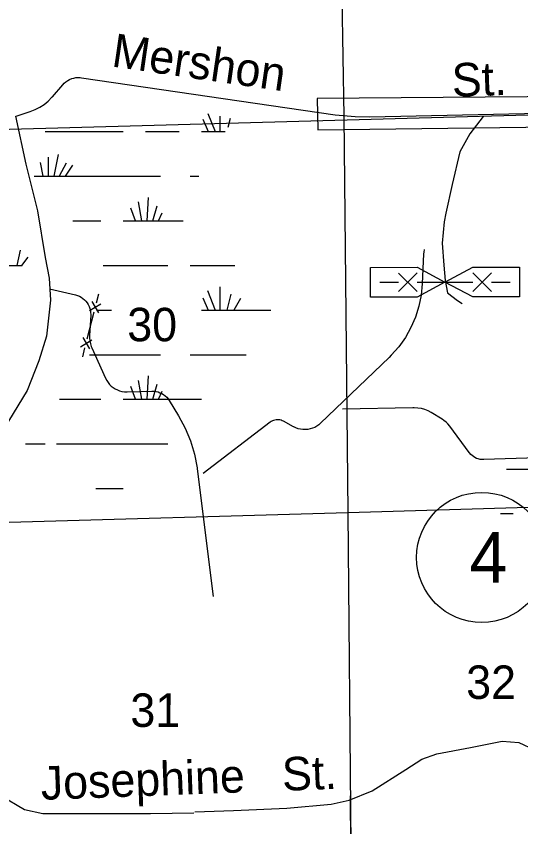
# Model space of a CAD drawing. Extents: x 2480962 to 2688785, y 277103 to 599240.
# Drawn here: x 2550088 to 2556869, y 466056 to 476959 of the extents above; entities that cross this region are included whole.
import ezdxf

# ---------------------------------------------------------------- set-up
doc = ezdxf.new("R2010")
doc.units = 0
for name, color, linetype in [('County Routes Highway Center Lines', 7, 'Continuous'), ('Level 31', 7, 'Continuous'), ('Level 36', 7, 'Continuous'), ('Local Roads Improved', 7, 'Continuous'), ('Local Roads Paved', 7, 'Continuous'), ('Local Roads Related Cells', 7, 'Continuous'), ('Local Roads Related Text', 7, 'Continuous'), ('Planning Number US Highways', 7, 'Continuous'), ('Section Lines', 7, 'Continuous'), ('Section Numbers', 7, 'Continuous'), ('Swamps', 7, 'Continuous'), ('Uninventoried Roads and Features', 7, 'Continuous')]:
    doc.layers.add(name, color=color, linetype=linetype)

msp = doc.modelspace()

# ---------------------------------------------------------------- linework, layer by layer
at = {"layer": 'County Routes Highway Center Lines'}
msp.add_lwpolyline([(2550077.701, 475613.011), (2550216.979, 474968.85), (2550373.667, 474342.099), (2550478.125, 473715.349), (2550530.354, 473436.793), (2550547.764, 473140.827), (2550495.535, 472653.354), (2550391.076, 472322.569), (2550234.389, 471922.145), (2549677.277, 471016.839)], dxfattribs=at)
at = {"layer": 'Level 31'}
msp.add_lwpolyline([(2554131.306, 475851.398), (2554140.859, 475431.033), (2561478.147, 475526.57), (2561468.594, 475908.721)], close=True, dxfattribs=at)
at = {"layer": 'Local Roads Improved'}
for p, q in [((2550574.066, 475875.992), (2550712.997, 476037.141)), ((2550966.278, 476131.608), (2554372.544, 475633.102)), ((2550088.588, 475614.656), (2550276.443, 475676.887)), ((2554841.342, 475607.588), (2557323.814, 475657.805))]:
    msp.add_line(p, q, dxfattribs=at)
for points in [[(2550712.997, 476037.141), (2550733.322, 476058.362), (2550755.756, 476077.343), (2550780.05, 476093.874), (2550805.94, 476107.776), (2550833.139, 476118.895), (2550861.353, 476127.111), (2550890.271, 476132.332), (2550919.577, 476134.502), (2550948.948, 476133.597), (2550966.278, 476131.608)], [(2550276.443, 475676.887), (2550341.96, 475702.469), (2550404.445, 475734.76), (2550463.212, 475773.405), (2550517.617, 475817.981), (2550567.066, 475868), (2550574.066, 475875.992)], [(2554372.544, 475633.102), (2554641.926, 475607.988), (2554841.342, 475607.588)], [(2556361.859, 475611.875), (2556182.54, 475378.216), (2556052.125, 475133.689), (2555948.881, 474693.541), (2555861.938, 474307.733), (2555840.202, 474193.62), (2555813.033, 473905.622), (2555834.768, 473612.19), (2555851.07, 473405.701), (2555883.674, 473237.249), (2556019.522, 473134.005), (2556079.295, 473095.967)], [(2548078.861, 467406.752), (2548396.986, 467337.387), (2548538.109, 467248.886), (2548621.826, 467203.439), (2548960.803, 467198.102), (2549045.534, 467145.145), (2549236.178, 466996.867), (2549373.865, 466816.814), (2549543.326, 466679.127), (2549882.249, 466477.892), (2550199.989, 466287.248), (2550443.589, 466234.291), (2551894.601, 466234.291), (2552477.124, 466244.882)]]:
    msp.add_lwpolyline(points, dxfattribs=at)
at = {"layer": 'Local Roads Paved'}
msp.add_lwpolyline([(2552487.715, 466255.474), (2553006.69, 466276.656), (2553726.9, 466308.43), (2554320.015, 466361.387), (2554563.615, 466414.344), (2554870.764, 466541.44), (2555326.191, 466827.405), (2555538.017, 466965.093), (2555739.252, 467039.232), (2556194.679, 467123.962), (2556618.332, 467208.693), (2556840.75, 467187.51), (2557052.577, 467092.189), (2557338.543, 466827.405), (2557455.047, 466732.083)], dxfattribs=at)
at = {"layer": 'Local Roads Related Cells'}
for p, q in [((2554850.202, 473580.809), (2555475.201, 473581.502)), ((2554850.645, 473180.809), (2554850.202, 473580.809)), ((2555475.201, 473581.502), (2555850.422, 473381.918)), ((2555850.422, 473381.918), (2556225.199, 473582.333)), ((2556225.199, 473582.333), (2556850.198, 473583.026)), ((2556850.198, 473583.026), (2556850.642, 473183.026)), ((2555225.288, 473503.916), (2555475.564, 473254.193)), ((2555475.285, 473506.502), (2555225.561, 473256.225)), ((2556225.282, 473507.334), (2556475.559, 473257.611)), ((2556475.282, 473507.611), (2556225.559, 473257.333)), ((2554975.423, 473380.948), (2555225.423, 473381.225)), ((2555475.423, 473381.503), (2556225.42, 473382.334)), ((2555850.422, 473381.918), (2555475.645, 473181.502)), ((2556225.642, 473182.333), (2555850.422, 473381.918)), ((2556475.421, 473382.611), (2556725.42, 473382.888)), ((2555475.645, 473181.502), (2554850.645, 473180.809)), ((2556850.642, 473183.026), (2556225.642, 473182.333))]:
    msp.add_line(p, q, dxfattribs=at)
at = {"layer": 'Planning Number US Highways'}
msp.add_circle((2556343.773, 469679.064), 875, dxfattribs=at)
at = {"layer": 'Section Lines'}
for p, q in [((2554408.973, 480881.504), (2554490.054, 475616.399)), ((2549192.299, 475416.768), (2559805.122, 475712.924)), ((2554490.298, 475612.903), (2554543.75, 470285.388)), ((2554543.75, 470285.388), (2559876.743, 470442.978)), ((2549221.245, 470131.992), (2554543.75, 470285.388)), ((2554543.75, 470285.388), (2554589.041, 465187.392))]:
    msp.add_line(p, q, dxfattribs=at)
at = {"layer": 'Swamps'}
for p, q in [((2552596.155, 475572.177), (2552666.968, 475406.162)), ((2550477.067, 475406.126), (2551527.064, 475406.143)), ((2551827.063, 475406.148), (2552277.062, 475406.156)), ((2550518.018, 475064.69), (2550518.021, 474806.129)), ((2550650.922, 475100.938), (2550591.985, 474806.235)), ((2550409.278, 474992.194), (2550446.489, 474806.149)), ((2550759.663, 474980.118), (2550665.658, 474805.531)), ((2550844.239, 474955.954), (2550744.921, 474806.974)), ((2550327.076, 474806.125), (2552027.071, 474806.153)), ((2551848.588, 474206.184), (2551865.824, 474522.257)), ((2551777.588, 474206.233), (2551731.333, 474460.613)), ((2551925.274, 474206.363), (2551983.506, 474410.182)), ((2551692.515, 474206.32), (2551627.042, 474378.185)), ((2552001.87, 474206.286), (2552050.753, 474314.919)), ((2550100.356, 473605.935), (2550143.24, 473811.786)), ((2552427.086, 473606.163), (2553027.084, 473606.172)), ((2552825.747, 473317.174), (2552825.751, 473006.171)), ((2552656.596, 473268.842), (2552759.618, 473006.17)), ((2552970.735, 473220.519), (2552917.126, 473006.071)), ((2552596.187, 473172.184), (2552667, 473006.168)), ((2553103.64, 473160.11), (2553013.923, 473006.303)), ((2552427.102, 472406.166), (2553177.099, 472406.178)), ((2551848.621, 471806.19), (2551865.856, 472122.263)), ((2551777.621, 471806.239), (2551731.366, 472060.619)), ((2551925.306, 471806.369), (2551983.538, 472010.189)), ((2551692.547, 471806.326), (2551627.074, 471978.191)), ((2552001.902, 471806.292), (2552050.786, 471914.925)), ((2551527.113, 471806.153), (2552577.109, 471806.17)), ((2550627.124, 471206.139), (2552127.119, 471206.164)), ((2554589.361, 465288.644), (2554582.256, 466471.515))]:
    msp.add_line(p, q, dxfattribs=at)
for points in [[(2552663.499, 475651.15), (2552759.585, 475406.163)], [(2552825.716, 475614.183), (2552825.719, 475406.164)], [(2552961.39, 475583.264), (2552931.028, 475461.808)], [(2552577.061, 475406.16), (2552898.183, 475406.166)], [(2552427.069, 474806.16), (2552544.001, 474806.161)], [(2550850.336, 474206.135), (2551227.081, 474206.142)], [(2551527.08, 474206.146), (2552329.495, 474206.16)], [(2550162.552, 473605.628), (2550246.329, 473719.329)], [(2549727.094, 473606.119), (2550169.222, 473606.126)], [(2551258.073, 473606.144), (2552127.086, 473606.158)], [(2551166.289, 473006.144), (2551370.482, 473006.147)], [(2552577.093, 473006.167), (2553510.117, 473006.182)], [(2551074.506, 472406.144), (2552027.103, 472406.159)], [(2550667.825, 471806.139), (2551227.114, 471806.148)], [(2550213.164, 471206.133), (2550477.124, 471206.137)], [(2556675.874, 470868.174), (2557367.11, 470868.186)], [(2551159.365, 470606.15), (2551527.129, 470606.156)], [(2556594.543, 470268.175), (2556767.119, 470268.177)]]:
    msp.add_lwpolyline(points, dxfattribs=at)
at = {"layer": 'Uninventoried Roads and Features'}
for p, q in [((2555562.72, 473760.664), (2555545.3, 473359.869)), ((2550535.56, 473292.708), (2550884.599, 473210.49)), ((2551165.642, 473104.411), (2551196.337, 473225.584)), ((2551074.36, 472998.586), (2551226.228, 473089.063)), ((2551105.055, 473119.759), (2551195.533, 472967.89)), ((2551042.861, 472619.719), (2551134.947, 472983.238)), ((2551088.676, 472937.044), (2551073.117, 472665.263)), ((2550951.579, 472513.894), (2551103.447, 472604.372)), ((2550982.274, 472635.067), (2551072.752, 472483.199)), ((2550981.47, 472377.373), (2551012.165, 472498.546)), ((2551104.361, 472497.353), (2551289.598, 472088.197)), ((2555098.345, 472369.538), (2554178.758, 471484.364)), ((2551580.235, 471906.182), (2551912.183, 471915.035)), ((2552144.241, 471789.276), (2552270.471, 471583.797)), ((2555419.405, 471692.162), (2554471.544, 471671.054)), ((2555812.901, 471538.297), (2555666.44, 471626.484)), ((2553500.436, 471496.721), (2552602.297, 470808.426)), ((2553814.558, 471435.999), (2553679.281, 471510.304)), ((2556175.718, 471089.387), (2555913.782, 471446.225)), ((2557093.226, 471020.372), (2556370.367, 470995.052)), ((2552521.3, 470868.943), (2552735.124, 469153.87))]:
    msp.add_line(p, q, dxfattribs=at)
for points in [[(2555570.626, 473822.593), (2555564.458, 473783.927), (2555562.72, 473760.664)], [(2555545.3, 473359.869), (2555530.655, 473207.463), (2555500.159, 473057.423), (2555454.147, 472911.392), (2555393.124, 472770.97), (2555317.756, 472637.697), (2555228.87, 472513.031), (2555127.44, 472398.34), (2555098.345, 472369.538)], [(2550884.599, 473210.49), (2550911.264, 473202.716), (2550936.97, 473192.196), (2550961.435, 473179.048), (2550984.392, 473163.414), (2551005.589, 473145.467), (2551024.793, 473125.402), (2551041.797, 473103.439), (2551056.41, 473079.82), (2551068.474, 473054.802), (2551077.858, 473028.66), (2551084.457, 473001.68), (2551088.2, 472974.159), (2551089.046, 472946.398), (2551088.676, 472937.044)], [(2551073.117, 472665.263), (2551072.937, 472627.835), (2551076.669, 472590.594), (2551084.274, 472553.947), (2551095.668, 472518.296), (2551104.361, 472497.353)], [(2551289.598, 472088.197), (2551304.507, 472059.381), (2551322.347, 472032.282), (2551342.923, 472007.195), (2551366.008, 471984.397), (2551391.349, 471964.137), (2551418.669, 471946.636), (2551447.669, 471932.088), (2551478.031, 471920.649), (2551509.422, 471912.448), (2551541.498, 471907.574), (2551573.908, 471906.077), (2551580.235, 471906.182)], [(2551912.183, 471915.035), (2551939.816, 471914.324), (2551967.224, 471910.73), (2551994.106, 471904.289), (2552020.168, 471895.074), (2552045.123, 471883.186), (2552068.699, 471868.753), (2552090.637, 471851.937), (2552110.698, 471832.918), (2552128.661, 471811.906), (2552144.241, 471789.276)], [(2555666.44, 471626.484), (2555624.031, 471649.083), (2555579.492, 471667.125), (2555533.311, 471680.413), (2555485.995, 471688.802), (2555438.06, 471692.198), (2555419.405, 471692.162)], [(2552270.471, 471583.797), (2552359.973, 471419.39), (2552431.799, 471246.528), (2552485.164, 471067.104), (2552519.48, 470883.085), (2552521.3, 470868.943)], [(2553679.281, 471510.304), (2553663.812, 471517.774), (2553647.647, 471523.588), (2553630.962, 471527.68), (2553613.941, 471530.004), (2553596.77, 471530.538), (2553579.638, 471529.274), (2553562.731, 471526.226), (2553546.236, 471521.426), (2553530.332, 471514.929), (2553515.195, 471506.806), (2553500.991, 471497.145), (2553500.436, 471496.721)], [(2554178.758, 471484.364), (2554154.236, 471463.116), (2554127.627, 471444.549), (2554099.225, 471428.866), (2554069.338, 471416.236), (2554038.294, 471406.8), (2554006.435, 471400.66), (2553974.108, 471397.885), (2553941.668, 471398.503), (2553909.471, 471402.509), (2553877.869, 471409.859), (2553847.207, 471420.472), (2553817.823, 471434.231), (2553814.558, 471435.999)], [(2555913.782, 471446.225), (2555890.752, 471474.381), (2555864.907, 471499.974), (2555836.527, 471522.727), (2555812.901, 471538.297)], [(2556370.367, 470995.052), (2556346.148, 470995.473), (2556322.106, 470998.421), (2556298.504, 471003.868), (2556275.6, 471011.751), (2556253.646, 471021.986), (2556232.882, 471034.46), (2556213.536, 471049.035), (2556195.82, 471065.553), (2556179.926, 471083.832), (2556175.718, 471089.387)]]:
    msp.add_lwpolyline(points, dxfattribs=at)

# ---------------------------------------------------------------- texts
at = {"layer": 'Level 36'}
msp.add_text('32', height=450, rotation=359.9794417, dxfattribs=at).set_placement((2556135.504, 467775.979))
at = {"layer": 'Local Roads Related Text'}
for s, rotation, p in [('Mershon', 351.7611639, (2551357.062, 476284.429)), ('St.', 2.0009306, (2555949.567, 475874.645)), ('Josephine   St.', 2.1593083, (2550425.502, 466417.126))]:
    msp.add_text(s, height=450, rotation=rotation, dxfattribs=at).set_placement(p)
at = {"layer": 'Planning Number US Highways'}
msp.add_text('4', height=680, dxfattribs=at).set_placement((2556181.011, 469339.067))
at = {"layer": 'Section Numbers'}
for s, rotation, p in [('30', 359.9794333, (2551580.393, 472586.678)), ('31', 359.9794417, (2551622.121, 467399.455))]:
    msp.add_text(s, height=450, rotation=rotation, dxfattribs=at).set_placement(p)

doc.saveas('drawing.dxf')
